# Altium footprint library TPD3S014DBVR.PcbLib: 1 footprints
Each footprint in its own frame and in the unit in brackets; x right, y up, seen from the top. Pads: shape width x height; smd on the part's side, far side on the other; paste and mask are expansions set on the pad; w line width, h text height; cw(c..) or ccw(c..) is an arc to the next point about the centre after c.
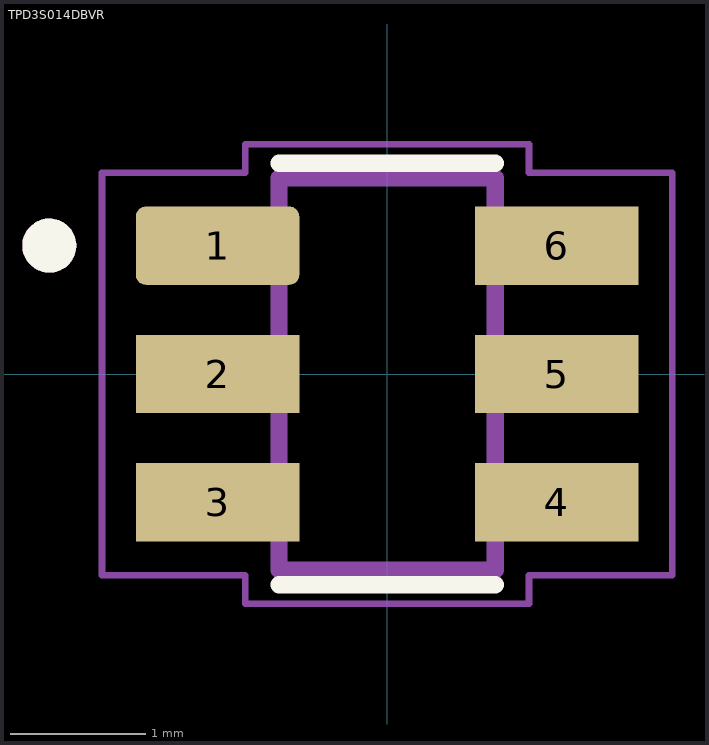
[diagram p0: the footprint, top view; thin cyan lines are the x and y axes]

## TPD3S014DBVR [mm]
pads (6):
  rrect25% 1.21x0.58 smd: 1(-1.255,0.95)
  rect 1.21x0.58 smd: 2(-1.255,0) 3(-1.255,-0.95) 4(1.255,-0.95) 5(1.255,0) 6(1.255,0.95)
Top Overlay:
  circle w0.2: c-2.5,0.95 r0.1
  lines w0.127: -0.8,-1.56 0.8,-1.56 ; -0.8,1.56 0.8,1.56
Mechanical 13:
  circle w0.2: c-2.5,0.95 r0.1
  lines w0.127: -0.8,-1.45 0.8,-1.45 0.8,1.45 -0.8,1.45 -0.8,-1.45
Mechanical 15:
  lines w0.05: -2.11,-1.49 -1.05,-1.49 -1.05,-1.7 1.05,-1.7 1.05,-1.49 2.11,-1.49 2.11,1.49 1.05,1.49 1.05,1.7 -1.05,1.7 -1.05,1.49 -2.11,1.49 -2.11,-1.49
3D body "TPD3S014DBVR.STEP": height 1.45, standoff 0, extent -1.404,-1.455 1.396,1.445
